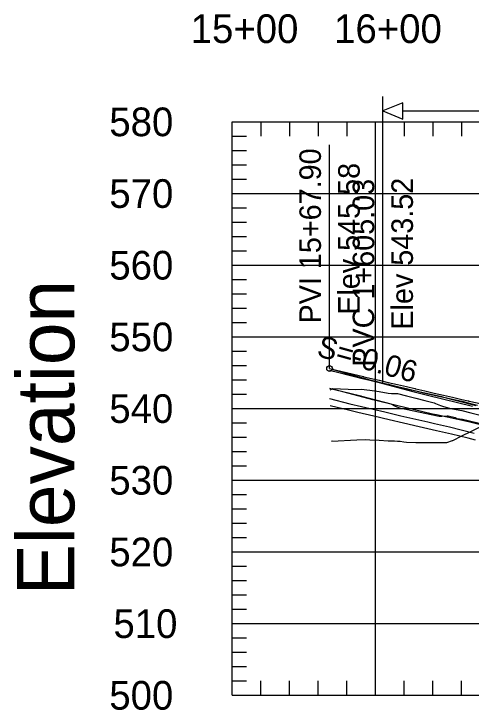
# Model space of a CAD drawing. Extents: x 704834 to 709892, y 372981 to 377533.
# Drawn here: x 706548.3 to 706867, y 375262.2 to 375747.7 of the extents above; entities that cross this region are included whole.
import ezdxf

# ---------------------------------------------------------------- set-up
doc = ezdxf.new("R2010")
doc.units = 0
for name, color, linetype in [('1', 7, 'Continuous'), ('10', 7, 'Continuous'), ('12', 7, 'Continuous'), ('13', 7, 'Continuous'), ('20', 7, 'Continuous'), ('42', 7, 'Continuous'), ('49', 7, 'Continuous'), ('61', 7, 'Continuous'), ('63', 7, 'Continuous'), ('Existing', 7, 'Continuous')]:
    doc.layers.add(name, color=color, linetype=linetype)

msp = doc.modelspace()

# ---------------------------------------------------------------- linework, layer by layer
at = {"layer": '10'}
for points in [[(706768.3, 375486.59), (706768.87, 375486.45), (706790.08, 375481.29), (706790.08, 375481.28), (706790.13, 375481.27), (706790.46, 375481.19), (706810.94, 375475.81), (706814, 375474.11), (706817.05, 375473.04), (706844.79, 375467.23), (706846.69, 375467.12), (706850.24, 375467.44), (706850.89, 375467.3), (706855.8, 375466.26), (706856.94, 375465.45), (706860.99, 375465.14), (706876.59, 375461.44)], [(706886.22, 375457.98), (706865.07, 375463.11), (706842.92, 375468.01), (706840.08, 375468.68), (706832.36, 375470.41), (706810.1, 375475.68), (706798.5, 375478.65), (706777.57, 375484.04), (706769.64, 375485.97)]]:
    msp.add_lwpolyline(points, dxfattribs=at)
at = {"layer": '12'}
msp.add_lwpolyline([(706768.3, 375479.58), (706768.34, 375479.57), (706782.47, 375475.88), (706790.68, 375473.94), (706806.75, 375470.09), (706817.89, 375467.42), (706836.83, 375463.16), (706841.41, 375462.17), (706851.88, 375459.74), (706869.18, 375455.39)], dxfattribs=at)
at = {"layer": '13'}
msp.add_lwpolyline([(706870.1, 375450.5), (706864.99, 375451.78), (706853.21, 375454.53), (706842.77, 375456.87), (706830.7, 375459.62), (706819.82, 375462.22), (706809.8, 375464.52), (706799.21, 375467.07), (706787.96, 375469.76), (706780.54, 375471.53), (706777.51, 375472.24), (706768.78, 375474.29)], dxfattribs=at)
at = {"layer": '42'}
for p, q in [((706805.44, 375490.05), (706805.44, 375690.05)), ((706768.3, 375500.36), (706768.3, 375656.36)), ((706768.3, 375500.36), (706805.44, 375490.05))]:
    msp.add_line(p, q, dxfattribs=at)
msp.add_lwpolyline([(706805.44, 375680.05), (706819.3, 375674.31), (706819.3, 375685.79)], close=True, dxfattribs=at)
for points in [[(706819.3, 375680.05), (707291.58, 375680.05)], [(706805.44, 375490.05), (706815.85, 375487.21), (706826.27, 375484.44), (706836.69, 375481.76), (706847.1, 375479.16), (706857.52, 375476.64), (706867.94, 375474.2)]]:
    msp.add_lwpolyline(points, dxfattribs=at)
msp.add_circle((706768.3, 375500.36), 2, dxfattribs=at)
at = {"layer": '61'}
for p, q in [((706700.4, 375672.45), (709300.4, 375672.45)), ((706700.4, 375272.45), (706700.4, 375672.45)), ((706720.4, 375672.45), (706720.4, 375662.45)), ((706740.4, 375672.45), (706740.4, 375662.45)), ((706760.4, 375672.45), (706760.4, 375662.45)), ((706780.4, 375672.45), (706780.4, 375662.45)), ((706800.4, 375272.45), (706800.4, 375672.45)), ((706820.4, 375672.45), (706820.4, 375662.45)), ((706840.4, 375672.45), (706840.4, 375662.45)), ((706860.4, 375672.45), (706860.4, 375662.45)), ((706700.4, 375662.45), (706710.4, 375662.45)), ((706700.4, 375652.45), (706710.4, 375652.45)), ((706700.4, 375642.45), (706710.4, 375642.45)), ((706700.4, 375632.45), (706710.4, 375632.45)), ((706700.4, 375622.45), (709300.4, 375622.45)), ((706700.4, 375612.45), (706710.4, 375612.45)), ((706700.4, 375602.45), (706710.4, 375602.45)), ((706700.4, 375592.45), (706710.4, 375592.45)), ((706700.4, 375582.45), (706710.4, 375582.45)), ((706700.4, 375572.45), (709300.4, 375572.45)), ((706700.4, 375562.45), (706710.4, 375562.45)), ((706700.4, 375552.45), (706710.4, 375552.45)), ((706700.4, 375542.45), (706710.4, 375542.45)), ((706700.4, 375532.45), (706710.4, 375532.45)), ((706700.4, 375522.45), (709300.4, 375522.45)), ((706700.4, 375512.45), (706710.4, 375512.45)), ((706700.4, 375502.45), (706710.4, 375502.45)), ((706700.4, 375492.45), (706710.4, 375492.45)), ((706700.4, 375482.45), (706710.4, 375482.45)), ((706700.4, 375472.45), (709300.4, 375472.45)), ((706700.4, 375462.45), (706710.4, 375462.45)), ((706700.4, 375452.45), (706710.4, 375452.45)), ((706700.4, 375442.45), (706710.4, 375442.45)), ((706700.4, 375432.45), (706710.4, 375432.45)), ((706700.4, 375422.45), (709300.4, 375422.45)), ((706700.4, 375412.45), (706710.4, 375412.45)), ((706700.4, 375402.45), (706710.4, 375402.45)), ((706700.4, 375392.45), (706710.4, 375392.45)), ((706700.4, 375382.45), (706710.4, 375382.45)), ((706700.4, 375372.45), (709300.4, 375372.45)), ((706700.4, 375362.45), (706710.4, 375362.45)), ((706700.4, 375352.45), (706710.4, 375352.45)), ((706700.4, 375342.45), (706710.4, 375342.45)), ((706700.4, 375332.45), (706710.4, 375332.45)), ((706700.4, 375322.45), (709300.4, 375322.45)), ((706700.4, 375312.45), (706710.4, 375312.45)), ((706700.4, 375302.45), (706710.4, 375302.45)), ((706700.4, 375292.45), (706710.4, 375292.45)), ((706700.4, 375282.45), (706710.4, 375282.45)), ((706720.4, 375272.45), (706720.4, 375282.45)), ((706740.4, 375272.45), (706740.4, 375282.45)), ((706760.4, 375272.45), (706760.4, 375282.45)), ((706780.4, 375272.45), (706780.4, 375282.45)), ((706820.4, 375272.45), (706820.4, 375282.45)), ((706840.4, 375272.45), (706840.4, 375282.45)), ((706860.4, 375272.45), (706860.4, 375282.45)), ((706700.4, 375272.45), (709300.4, 375272.45))]:
    msp.add_line(p, q, dxfattribs=at)
at = {"layer": '63'}
for points in [[(706768.3, 375499.28), (706787.48, 375494.3), (706790.22, 375493.65), (706796.4, 375492.2), (706802.8, 375490.66), (706809.21, 375489.12), (706811.2, 375488.64), (706815.17, 375487.7), (706815.62, 375487.6), (706822.03, 375486.17), (706828.43, 375484.74), (706834.84, 375483.32), (706841.25, 375481.9), (706844.37, 375481.22), (706847.66, 375480.44), (706848.63, 375480.21), (706854.07, 375478.83), (706860.47, 375477.19), (706866.88, 375475.57), (706870.23, 375474.72)], [(706768.94, 375498.93), (706784.47, 375495.3), (706786.75, 375494.76), (706796.4, 375492.46), (706801.2, 375491.35), (706802.8, 375490.96), (706809.21, 375489.43), (706814.43, 375488.18), (706815.62, 375487.91), (706817.84, 375487.41), (706822.03, 375486.42), (706828.43, 375484.9), (706831.39, 375484.2), (706834.84, 375483.42), (706841.25, 375481.96), (706846.42, 375480.79), (706847.66, 375480.51), (706850.14, 375479.95), (706854.07, 375479.04), (706860.47, 375477.54), (706864.91, 375476.5), (706866.88, 375476.01), (706871.47, 375474.86)], [(706768.74, 375485.62), (706770.63, 375486.51), (706786.63, 375485.88), (706790.36, 375486.06), (706796.4, 375485.2), (706802.8, 375484.29), (706809.21, 375483.27), (706811.48, 375482.87), (706814.8, 375483.09), (706815.62, 375482.91), (706822.03, 375481.41), (706828.43, 375479.81), (706834.84, 375478.13), (706841.25, 375476.37), (706842.17, 375476.1), (706845.67, 375474.65), (706847.66, 375474.02), (706850.25, 375473.16), (706854.07, 375472.4), (706860.47, 375471.01), (706866.88, 375469.51), (706873.29, 375467.91)], [(706769.66, 375450.21), (706769.81, 375449.83), (706787.22, 375450.68), (706793.68, 375450.97), (706796.4, 375450.77), (706802.8, 375450.34), (706809.21, 375450.02), (706813.64, 375449.88), (706815.62, 375449.76), (706817.57, 375449.68), (706820.15, 375449.23), (706822.03, 375449.13), (706828.43, 375448.9), (706834.84, 375448.77), (706841.25, 375448.75), (706847.04, 375448.82), (706847.66, 375448.82), (706850.06, 375448.86), (706854.07, 375450.27), (706854.16, 375450.31), (706860.47, 375453.34), (706866.88, 375456.49), (706873.29, 375459.73)]]:
    msp.add_lwpolyline(points, dxfattribs=at)
at = {"layer": 'Existing'}
msp.add_lwpolyline([(706768.3, 375500.36), (706768.32, 375500.35), (706791.94, 375494.76), (706792.15, 375494.71), (706792.34, 375494.66), (706796.4, 375493.72), (706802.8, 375492.23), (706809.21, 375490.74), (706815.62, 375489.25), (706822.03, 375487.75), (706827.66, 375486.44), (706827.91, 375486.37), (706828.19, 375486.31), (706828.43, 375486.25), (706834.84, 375484.79), (706841.25, 375483.32), (706847.66, 375481.85), (706854.07, 375480.38), (706860.47, 375478.9), (706865.01, 375477.86), (706865.26, 375477.8), (706865.37, 375477.77), (706865.48, 375477.74), (706865.59, 375477.71), (706866.88, 375477.42), (706873.29, 375476)], dxfattribs=at)

# ---------------------------------------------------------------- texts
at = {"layer": '1'}
msp.add_text('Elevation', height=40, rotation=90, dxfattribs=at).set_placement((706590.4, 375342.21))
at = {"layer": '20'}
msp.add_text('S=-0.06', height=15, rotation=344.4965, dxfattribs=at).set_placement((706758.71, 375509.24))
at = {"layer": '49'}
for s, p in [('PVI 15+67.90', (706762.3, 375531.82)), ('Elev 545.58', (706789.3, 375537.87)), ('PVC 1+605.03', (706799.44, 375501.66)), ('Elev 543.52', (706826.44, 375527.53))]:
    msp.add_text(s, height=15, rotation=90, dxfattribs=at).set_placement(p)
at = {"layer": '61'}
for s, p in [('15+00', (706671.48, 375727.45)), ('16+00', (706771.48, 375727.45)), ('580', (706614.76, 375662.45)), ('580', (706614.76, 375662.45)), ('570', (706614.76, 375612.45)), ('560', (706614.76, 375562.45)), ('550', (706614.76, 375512.45)), ('540', (706614.76, 375462.45)), ('530', (706614.76, 375412.45)), ('520', (706614.76, 375362.45)), ('510', (706617.64, 375312.45)), ('500', (706614.76, 375262.45))]:
    msp.add_text(s, height=20, dxfattribs=at).set_placement(p)

doc.saveas('drawing.dxf')
